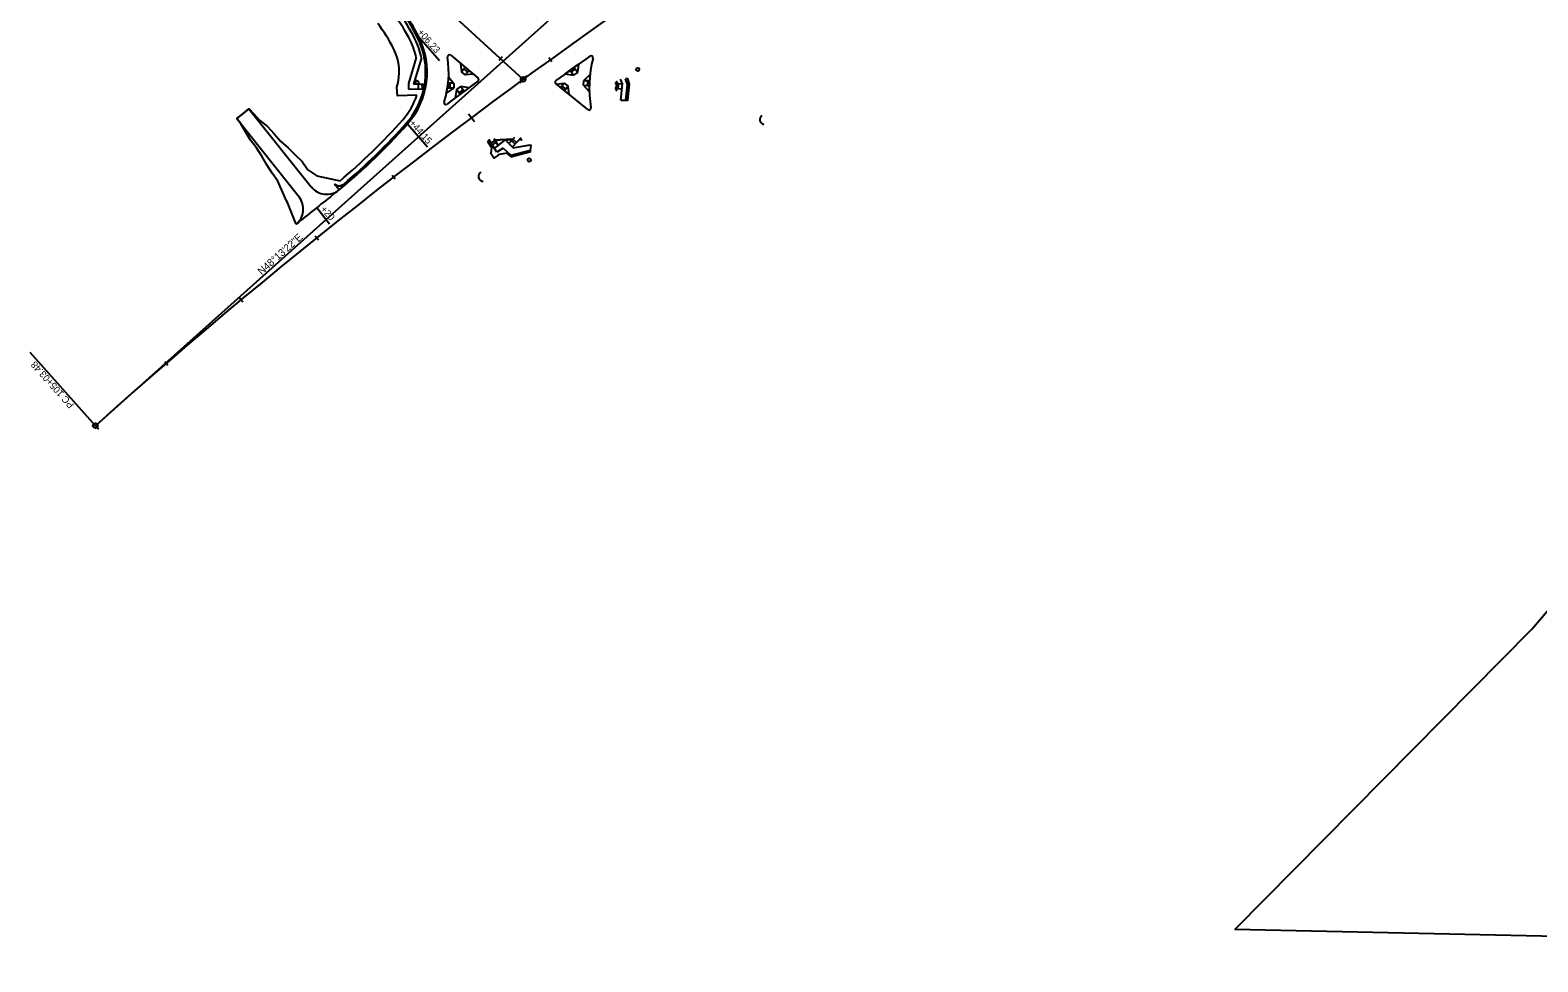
# Model space of a CAD drawing. Extents: x 1300404 to 1323571, y 237813 to 252077.
# Drawn here: x 1312220 to 1313760, y 237815 to 238766 of the extents above; entities that cross this region are included whole.
import ezdxf

# ---------------------------------------------------------------- set-up
doc = ezdxf.new("R2010")
doc.units = 0
for name, color, linetype in [('R_City Limits', 7, 'Continuous'), ('R_Const Limits', 7, 'Continuous'), ('R_Curb', 7, 'Continuous'), ('R_Flooplain', 7, 'Continuous'), ('R_Horz Alg Annot', 7, 'Continuous'), ('R_Horz Alg Annot Leader', 7, 'Continuous'), ('R_Horz Alg Major Ticks', 7, 'Continuous'), ('R_Horz Alg Minor Ticks', 7, 'Continuous'), ('R_Horz Alg Tangents', 7, 'Continuous'), ('R_Horz Alg Tangents Text', 7, 'Continuous'), ('R_Lane Edge', 7, 'Continuous'), ('R_Proposed', 7, 'Continuous'), ('R_Sidewalk Edge', 7, 'Continuous')]:
    doc.layers.add(name, color=color, linetype=linetype)

msp = doc.modelspace()

# ---------------------------------------------------------------- linework, layer by layer
at = {"layer": 'R_City Limits'}
for centre, start, end in [((1312969.9, 238674.5), 125.8858, 261.0437), ((1312682.5, 238616.5), 118.003, 269.5082)]:
    msp.add_arc(centre, 5, start, end, dxfattribs=at)
at = {"layer": 'R_Const Limits'}
for p, q in [((1312706.5, 238640.3), (1312697.3, 238638.6)), ((1312706.5, 238640.3), (1312710.5, 238636.4)), ((1312710.5, 238636.4), (1312731, 238641.8)), ((1312731, 238641.8), (1312730.9, 238643.4))]:
    msp.add_line(p, q, dxfattribs=at)
for points in [[(1312614.8, 238699.3), (1312594.9, 238698.7), (1312594.4, 238707.6)], [(1312831.8, 238710.5), (1312830, 238716), (1312827.9, 238716.1)], [(1312828.1, 238694.4), (1312830.1, 238694.2), (1312831.8, 238710.5)], [(1312491.4, 238567.6), (1312491.4, 238567.6), (1312491.4, 238567.6), (1312491.4, 238567.6), (1312491.4, 238567.6), (1312491.4, 238567.6), (1312491.4, 238567.6), (1312491.4, 238567.6), (1312482.6, 238590), (1312481.4, 238591.6), (1312481.4, 238591.6), (1312472.6, 238611.6), (1312467, 238619.9), (1312461.6, 238628.4), (1312456.4, 238637.1), (1312451, 238645.5), (1312444.9, 238653.4), (1312439.7, 238662.1), (1312434.5, 238670.8), (1312430.7, 238675.5), (1312437, 238680.5), (1312443.2, 238685.5), (1312443.4, 238685.6), (1312447.4, 238681.1), (1312454.2, 238673.7), (1312462.3, 238667.4), (1312468.9, 238659.8), (1312475.6, 238652.4), (1312483.1, 238645.6), (1312490.3, 238638.6), (1312497.7, 238631.6), (1312503.2, 238623.3), (1312512.5, 238617.1), (1312536.3, 238612), (1312536.3, 238612)], [(1312687.3, 238651.7), (1312690.9, 238645.9), (1312690.7, 238643.3), (1312690.4, 238640.2), (1312693.5, 238635.1), (1312697.8, 238637.9), (1312697.3, 238638.6)]]:
    msp.add_lwpolyline(points, dxfattribs=at)
for centre, radius, start, end in [((1312438.1, 238668.9), 171.5, 26.7854, 37.1377), ((1312545.2, 238723), 51.5, 342.6305, 26.7854), ((1312545.2, 238723), 73.5, 318.5363, 341.159), ((1312155.5, 239067.3), 593.5, 309.9072, 318.5363)]:
    msp.add_arc(centre, radius, start, end, dxfattribs=at)
at = {"layer": 'R_Curb'}
for p, q in [((1312623, 238712.8), (1312623.3, 238710.8)), ((1312819.1, 238713.4), (1312818.5, 238711.4)), ((1312818.6, 238713.4), (1312819.1, 238713.4)), ((1312621.3, 238703.7), (1312622.3, 238705.8)), ((1312818.8, 238704.3), (1312818.3, 238706.4)), ((1312818.3, 238704.4), (1312818.8, 238704.3)), ((1312687.3, 238651.7), (1312687, 238652.1)), ((1312687.3, 238651.7), (1312689.2, 238652.4)), ((1312697.1, 238653), (1312694.6, 238653.2)), ((1312709.4, 238653.9), (1312712.6, 238654.5)), ((1312721.4, 238653.6), (1312719.3, 238654.2)), ((1312721.9, 238654.1), (1312721.4, 238653.6))]:
    msp.add_line(p, q, dxfattribs=at)
for points in [[(1312818.5, 238711.4), (1312818.5, 238712.3), (1312818.6, 238713.4)], [(1312819, 238711.4), (1312819, 238712.2), (1312819.1, 238713.4)], [(1312818.3, 238704.4), (1312818.3, 238706.4)], [(1312818.8, 238704.3), (1312818.8, 238706.4)], [(1312689.2, 238652.4), (1312687, 238652.1)], [(1312689.5, 238652), (1312687.3, 238651.7)], [(1312712.6, 238654.5), (1312706.2, 238654.3), (1312699.8, 238653.8), (1312695.5, 238653.3), (1312694.6, 238653.2)], [(1312709.4, 238653.9), (1312706.2, 238653.8), (1312699.9, 238653.3), (1312697.1, 238653)], [(1312721.4, 238653.6), (1312718.8, 238653.7)], [(1312721.9, 238654.1), (1312719.3, 238654.2)]]:
    msp.add_lwpolyline(points, dxfattribs=at)
for centre, radius, start, end in [((1312438.1, 238668.9), 198.5, 26.7854, 45.5682), ((1312438.1, 238668.9), 199, 26.7854, 45.5682), ((1312545.2, 238723), 78.5, 352.5117, 26.7854), ((1312545.2, 238723), 79, 351.0957, 26.7854), ((1312545.2, 238723), 78.5, 318.5363, 345.8042), ((1312545.2, 238723), 79, 318.5363, 347.3955), ((1312155.5, 239067.3), 598.5, 309.9739, 318.5363), ((1312155.5, 239067.3), 599, 309.9739, 318.5363), ((1312535.5, 238614), 7.5, 228.63, 309.9741), ((1312535.5, 238614), 7, 229.3139, 309.9741)]:
    msp.add_arc(centre, radius, start, end, dxfattribs=at)
at = {"layer": 'R_Flooplain'}
for p, q in [((1313753.2, 238154.3), (1314141.3, 238611.4)), ((1313450, 237847.8), (1313753.2, 238154.3)), ((1315013.8, 237815), (1313450, 237847.8))]:
    msp.add_line(p, q, dxfattribs=at)
at = {"layer": 'R_Horz Alg Annot Leader'}
for points in [[(1312616.6, 238759), (1312637.9, 238734.9)], [(1312605.2, 238670), (1312625.7, 238646.8)], [(1312512.6, 238584.6), (1312525.6, 238568.1)], [(1312286.4, 238362.1), (1312219.8, 238436.7)]]:
    msp.add_lwpolyline(points, dxfattribs=at)
at = {"layer": 'R_Horz Alg Major Ticks'}
for points in [[(1312726.7, 238719.2), (1312719.9, 238711.8)], [(1312726.7, 238719.2), (1312719.9, 238711.8)], [(1312667.5, 238680.5), (1312673.5, 238672.4)], [(1312283.1, 238365.8), (1312289.7, 238358.4)], [(1312283.1, 238365.8), (1312289.7, 238358.4)]]:
    msp.add_lwpolyline(points, dxfattribs=at)
at = {"layer": 'R_Horz Alg Minor Ticks'}
for points in [[(1312701.8, 238738.5), (1312698.5, 238734.8)], [(1312749.6, 238737.7), (1312752.6, 238733.6)], [(1312589.5, 238617.8), (1312592.5, 238613.9)], [(1312511, 238555.8), (1312514.1, 238551.9)], [(1312433.6, 238492.4), (1312436.8, 238488.6)], [(1312357.3, 238427.7), (1312360.5, 238423.9)]]:
    msp.add_lwpolyline(points, dxfattribs=at)
at = {"layer": 'R_Horz Alg Tangents'}
msp.add_line((1312286.4, 238362.1), (1312884.9, 238896.8), dxfattribs=at)
at = {"layer": 'R_Lane Edge'}
for p, q in [((1312649.3, 238740.1), (1312677.2, 238716.9)), ((1312756.6, 238711), (1312789.1, 238684.6)), ((1312443.2, 238685.5), (1312430.7, 238675.5)), ((1312443.2, 238685.5), (1312506.9, 238605.7)), ((1312430.7, 238675.5), (1312494.5, 238595.7)), ((1312530.6, 238608.4), (1312531, 238608.7)), ((1312535.2, 238602.7), (1312530.6, 238608.4))]:
    msp.add_line(p, q, dxfattribs=at)
for centre, radius, start, end in [((1312438.1, 238668.9), 200, 26.7854, 45.5682), ((1312545.2, 238723), 80, 318.5363, 26.7854), ((1312545.2, 238723), 102, 342.5997, 8.637), ((1312648, 238738.6), 2, 50.127, 188.637), ((1316113.2, 234095.4), 5709.6, 125.5756, 126.0063), ((1312792.6, 238737.6), 2, 345.876, 125.5761), ((1312916.8, 238706.4), 126, 165.877, 189.0871), ((1316103.6, 234089.3), 5755.6, 126.53746, 126.92773), ((1312544.6, 238708.9), 102, 358.6814, 1.4854), ((1312544.6, 238708.9), 104, 358.6814, 1.4368), ((1312675.9, 238715.3), 2, 306.5375, 50.127), ((1312757.8, 238712.5), 2, 126.0063, 231.0012), ((1312644.4, 238691.9), 2, 162.5997, 306.9277), ((1312790.4, 238686.2), 2, 231.0012, 9.0871), ((1312155.5, 239067.3), 600, 308.4184, 318.5363), ((1312522.6, 238618.2), 20, 218.612, 309.2571), ((1316103.6, 234089.3), 5753.6, 128.41841, 128.88989), ((1312478.8, 238583.2), 20, 308.8899, 38.612)]:
    msp.add_arc(centre, radius, start, end, dxfattribs=at)
at = {"layer": 'R_Proposed'}
msp.add_line((1312638.6, 238793), (1312723.3, 238715.5), dxfattribs=at)
for centre, radius in [((1312840.3, 238725.7), 1.75), ((1312614.8, 238712.6), 1.75), ((1312723.3, 238715.5), 2.5), ((1312729.5, 238633.2), 1.75), ((1312286.4, 238362.1), 2.5)]:
    msp.add_circle(centre, radius, dxfattribs=at)
msp.add_arc((1316103.6, 234089.3), 5729.6, 115.83028, 131.77722, dxfattribs=at)
at = {"layer": 'R_Sidewalk Edge'}
for p, q in [((1312614.1, 238737.8), (1312606.1, 238711.2)), ((1312619.3, 238737.5), (1312611.1, 238710.6)), ((1312659.4, 238731.7), (1312660.2, 238723.2)), ((1312660.2, 238723.2), (1312662.7, 238726.3)), ((1312664, 238720), (1312660.2, 238723.2)), ((1312662.7, 238726.3), (1312664, 238727.9)), ((1312666.6, 238723.1), (1312662.7, 238726.3)), ((1312663.2, 238728.5), (1312668.6, 238724)), ((1312667.9, 238724.6), (1312664, 238727.9)), ((1312664, 238720), (1312666.6, 238723.1)), ((1312666.6, 238723.1), (1312667.9, 238724.6)), ((1312766.1, 238721), (1312779.9, 238731)), ((1312775.1, 238727.5), (1312771, 238724.5)), ((1312772.2, 238722.9), (1312771, 238724.5)), ((1312772.2, 238722.9), (1312776.2, 238725.8)), ((1312774.5, 238719.7), (1312772.2, 238722.9)), ((1312778.6, 238722.6), (1312774.5, 238719.7)), ((1312776.2, 238725.8), (1312775.1, 238727.5)), ((1312778.6, 238722.6), (1312776.2, 238725.8)), ((1312779.9, 238731), (1312778.6, 238722.6)), ((1312606.1, 238711.2), (1312606.1, 238705.6)), ((1312611.1, 238710.6), (1312624.3, 238710.8)), ((1312616.3, 238705.7), (1312616.2, 238710.7)), ((1312620.3, 238705.7), (1312620.2, 238710.7)), ((1312622.3, 238705.8), (1312622.2, 238710.8)), ((1312648.6, 238711.5), (1312646.6, 238711.6)), ((1312647.1, 238718), (1312652.6, 238711.4)), ((1312652.6, 238711.5), (1312648.6, 238711.5)), ((1312652.6, 238711.4), (1312652.5, 238706.5)), ((1312655.5, 238705.1), (1312659.5, 238708.1)), ((1312659.5, 238708.1), (1312661.9, 238704.9)), ((1312667.9, 238706.9), (1312659.5, 238708.1)), ((1312672.5, 238720.8), (1312664, 238720)), ((1312756.9, 238710.7), (1312765.3, 238711.6)), ((1312760.8, 238707.6), (1312766.2, 238703.2)), ((1312762.8, 238708.5), (1312761.6, 238707)), ((1312761.6, 238707), (1312765.4, 238703.8)), ((1312765.3, 238711.6), (1312762.8, 238708.5)), ((1312762.8, 238708.5), (1312766.7, 238705.4)), ((1312765.3, 238711.6), (1312769.2, 238708.5)), ((1312766.1, 238721), (1312774.5, 238719.7)), ((1312769.2, 238708.5), (1312766.7, 238705.4)), ((1312770.1, 238700), (1312769.2, 238708.5)), ((1312784.8, 238709.5), (1312785.1, 238714.5)), ((1312790.8, 238703), (1312784.8, 238709.5)), ((1312784.8, 238709.5), (1312788.8, 238709.3)), ((1312791.6, 238720.5), (1312785.1, 238714.5)), ((1312785.1, 238714.5), (1312789, 238714.3)), ((1312789, 238714.3), (1312788.8, 238709.3)), ((1312788.8, 238709.3), (1312790.8, 238709.2)), ((1312789, 238714.3), (1312791, 238714.2)), ((1312791, 238714.2), (1312790.8, 238709.2)), ((1312817, 238711.6), (1312824.8, 238710.8)), ((1312818.3, 238706.4), (1312818.8, 238711.4)), ((1312820.3, 238706.2), (1312820.8, 238711.2)), ((1312824.8, 238710.8), (1312822.6, 238715.8)), ((1312823.1, 238694.3), (1312824.8, 238710.8)), ((1312829.7, 238710.3), (1312827.9, 238716.1)), ((1312828.1, 238694.4), (1312829.7, 238710.3)), ((1312606.1, 238705.6), (1312623.3, 238705.8)), ((1312644.9, 238701.3), (1312652.5, 238706.5)), ((1312648.5, 238706.5), (1312645.9, 238706.6)), ((1312652.5, 238706.5), (1312648.5, 238706.5)), ((1312654.2, 238696.7), (1312655.5, 238705.1)), ((1312655.5, 238705.1), (1312657.8, 238701.9)), ((1312657.8, 238701.9), (1312661.9, 238704.9)), ((1312657.8, 238701.9), (1312659, 238700.3)), ((1312658.2, 238699.7), (1312663.9, 238703.9)), ((1312659, 238700.3), (1312663, 238703.3)), ((1312661.9, 238704.9), (1312663, 238703.3)), ((1312766.7, 238705.4), (1312765.4, 238703.8)), ((1312817, 238706.5), (1312824.2, 238705.8)), ((1312823.1, 238694.3), (1312828.1, 238694.4)), ((1312696.3, 238641.2), (1312688.2, 238654)), ((1312694.6, 238653.2), (1312690.4, 238650.5)), ((1312695.7, 238651.5), (1312691.5, 238648.8)), ((1312697.8, 238648.1), (1312693.6, 238654.8)), ((1312697.8, 238648.1), (1312693.6, 238645.4)), ((1312702.7, 238645.3), (1312696.3, 238641.2)), ((1312697.8, 238648.1), (1312705.2, 238653.7)), ((1312702.7, 238645.3), (1312710.5, 238638)), ((1312708.6, 238650.1), (1312705.3, 238653.7)), ((1312714.3, 238656.2), (1312708.6, 238650.1)), ((1312708.6, 238650.1), (1312713.1, 238645.8)), ((1312711.3, 238653), (1312714.9, 238649.6)), ((1312720.8, 238655.8), (1312712.2, 238646.7)), ((1312712.6, 238654.5), (1312716.3, 238651)), ((1312713.1, 238645.8), (1312730.3, 238648.6)), ((1312730.3, 238648.6), (1312731.4, 238648.4)), ((1312730.9, 238643.4), (1312731.4, 238648.4)), ((1312710.5, 238638), (1312730.9, 238643.4))]:
    msp.add_line(p, q, dxfattribs=at)
for centre, radius, start, end in [((1312438.1, 238668.9), 190.5, 26.7854, 45.5682), ((1312438.1, 238668.9), 195.5, 26.7854, 45.5682), ((1312545.2, 238723), 70.5, 12.1029, 26.7854), ((1312545.2, 238723), 75.5, 11.1056, 26.7854), ((1312916.8, 238706.4), 126, 173.5931, 181.5625)]:
    msp.add_arc(centre, radius, start, end, dxfattribs=at)

# ---------------------------------------------------------------- texts
at = {"layer": 'R_Horz Alg Annot'}
for s, rotation, p in [('+06.23', 311.4187, (1312614.9, 238763.2)), ('+44.15', 311.4187, (1312606.5, 238670.5)), ('+20', 311.4187, (1312515.9, 238582.6)), ('PC 105+03.48', 131.7772, (1312265.1, 238383.7))]:
    msp.add_text(s, height=7, rotation=rotation, dxfattribs=at).set_placement(p)
at = {"layer": 'R_Horz Alg Tangents Text'}
msp.add_text('N48%%d13\'22"E', height=7.5, rotation=41.7772, dxfattribs=at).set_placement((1312456.2, 238515.5))

doc.saveas('drawing.dxf')
